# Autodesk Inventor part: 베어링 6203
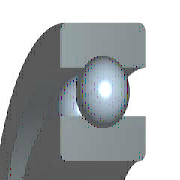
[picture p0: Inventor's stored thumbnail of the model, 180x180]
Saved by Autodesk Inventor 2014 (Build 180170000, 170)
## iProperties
IsCustomPart: 0
Created: 2014-10
Part Number: 베어링 6203
Material: 알루미늄 6061
Description: 깊은 그루브 볼 베어링
Document SubType Name: Modeling
Standard: KS B 2023
Designer: KYOUNG IL JANG
Standards Organization: KS
Language: ko-KR
Size Designation: 6203 - 17 x 40 x 12
Categories: <MemberInstance><Categories><Category DisplayName="샤프트 부품" InternalName="7f7aeb1f-a693-4053-b835-cee3144e0d98" Mnemonic="SHFT"><Category DisplayName="베어링" Inter
Density: 2.71 g/cm^3
Mass: 22.4044 g
Surface Area: 64.3582 cm^2
Volume: 8.26729 cm^3
Appearance: 알루미늄 - 평지
Author: SeoGD™ [www.esajin.kr]
Revision Number: 1
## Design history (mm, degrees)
sketch "스케치" dims "d0" = 5.98 (= -0.26 x WD + 0.26 x BD)
  geometry: L1 (3.01, 14.25)-(8.99, 14.25); L2 (6, 14.25)-(6, 11.26); L3 (6, 14.25)-(6, 17.24); L4 (3.778, 12.249)-(0, 12.249); L5 (0, 8.5)-(12, 8.5); L6 (3.778, 16.251)-(0, 16.251); L7 (0, 20)-(12, 20); L8 (12, 8.5)-(12, 12.249); L9 (8.222, 12.249)-(12, 12.249); L10 (8.222, 16.251)-(12, 16.251); L11 (12, 20)-(12, 16.251); L12 (-1.4, 0)-(8.4, 0) reference; L13 (0, -0.3)-(0, 5.3) reference
  constraints: 22 end point, 4 point on line, 2 collinear, 2 perpendicular, 2 symmetric about line, 1 midpoint, 1 parallel, 14 other
  dimensions: "d9" = 17 diameter of L5 L12 (= WD); "d11" = 40 diameter of L7 L12 (= BD); "d12" = 12 distance between parallel lines of L8 L13 (= KB); "d13" = 24.498 diameter of L9 L12 (= 0.326 x BD + 0.674 x WD)
revolve "본체" stored, may be unused: angle "d6" = 90 deg
revolve "볼" stored, may be unused: angle "d7" = 90 deg
pattern_circular "IDS_ARRAYBALL[SIMPL:T]" dims angle "d3" = 360 deg
body "Solid1"
fillet "모깎기1" dims "d1" = 0.6 (= KRS)
other parameters: "WD" = 17 [user parameter; used in 5 equation terms], "BD" = 40 [user parameter; used in 5 equation terms], "KB" = 12 [user parameter; used in 1 equation term], "KRS" = 0.6 [user parameter; used in 1 equation term], "d4" = 0, "d5" = 0, "d8" = 0, "d14" = 0, "d15" = 0, "BBA" = 0 [user parameter], "BC0" = 4750000 [user parameter], "BC" = 9560000 [user parameter], "WR" = 8.5 (= 0.5 x WD) [user parameter]
